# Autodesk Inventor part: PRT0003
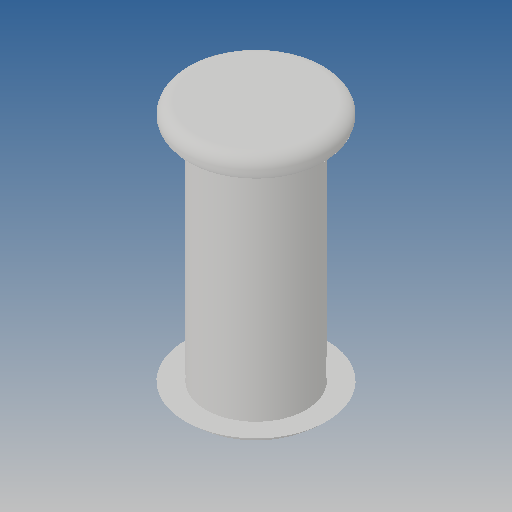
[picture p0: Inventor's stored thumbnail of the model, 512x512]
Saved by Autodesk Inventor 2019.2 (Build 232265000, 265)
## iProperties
Created: 2012-06
Part Number: PRT0003
Material: Ogólny
Document SubType Name: Modeling
Designer: CADENGINEERING4
Density: 1 g/cm^3
Appearance: Domyślna
Author: CADENGINEERING4
Revision Number: 1LAST_VERSION
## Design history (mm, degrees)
feature "Baza1"
node "Bryła1"
